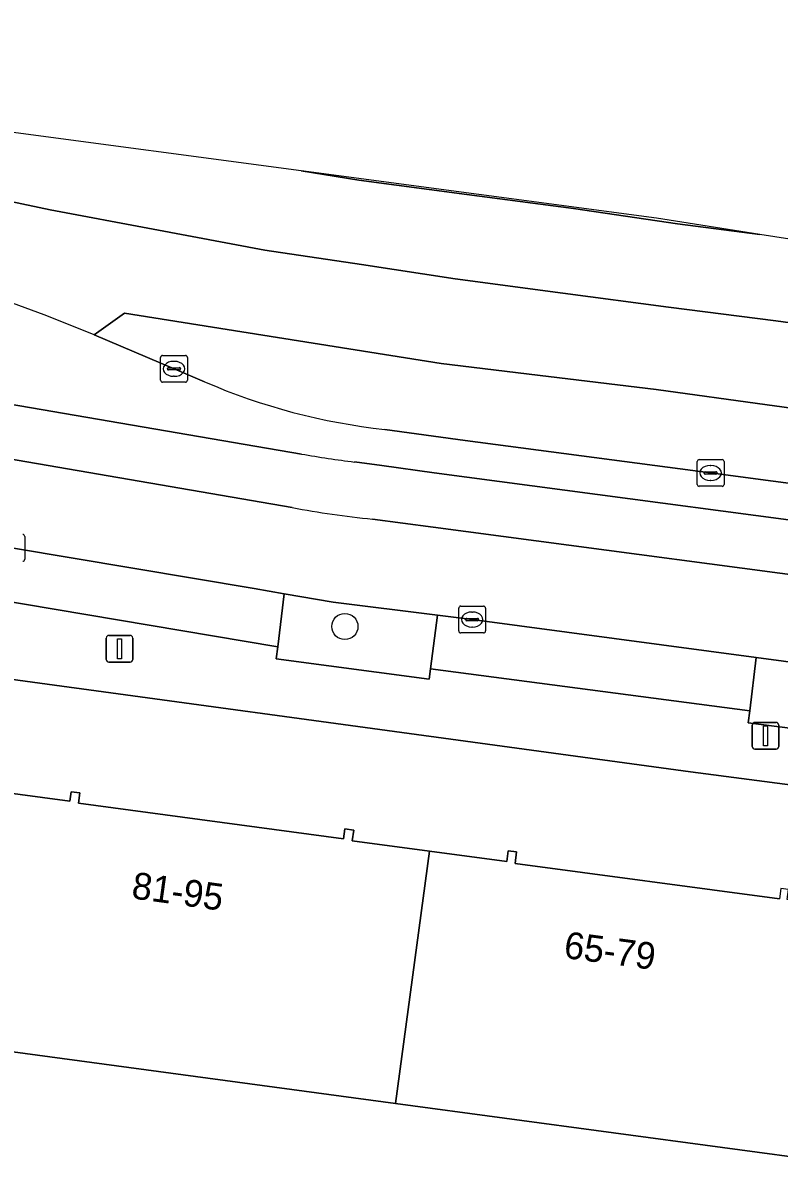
# Model space of a CAD drawing. Extents: x 161258 to 161838, y 380833 to 381727.
# Drawn here: x 161691.79 to 161720.06, y 381630.65 to 381673.22 of the extents above; entities that cross this region are included whole.
import ezdxf

# ---------------------------------------------------------------- set-up
doc = ezdxf.new("R2010")
doc.units = 0
for name, color, linetype in [('IMGEO_Berm_groen', 7, 'Continuous'), ('IMGEO_Boom', 7, 'Continuous'), ('IMGEO_Erf', 7, 'Continuous'), ('IMGEO_Groenvoorziening', 7, 'Continuous'), ('IMGEO_Kolk', 7, 'Continuous'), ('IMGEO_Lichtmast', 7, 'Continuous'), ('IMGEO_Pand', 7, 'Continuous'), ('IMGEO_Pand_nummerreeks', 7, 'Continuous'), ('IMGEO_Parkeervlak_halfverhard', 7, 'Continuous'), ('IMGEO_Parkeervlak_open', 7, 'Continuous'), ('IMGEO_Rijbaan_lokaal_open', 7, 'Continuous'), ('IMGEO_Rijbaan_regionaal_gesloten', 7, 'Continuous'), ('IMGEO_Voetpad_open', 7, 'Continuous')]:
    doc.layers.add(name, color=color, linetype=linetype)

msp = doc.modelspace()

# ---------------------------------------------------------------- linework, layer by layer
at = {"layer": 'IMGEO_Berm_groen'}
for points in [[(161698.584, 381659.806), (161697.441, 381660.29), (161694.46, 381661.561)], [(161690.364, 381659.132), (161702.211, 381657.106)], [(161751.562, 381651.859), (161748.27, 381652.294), (161735.854, 381653.957), (161717.493, 381656.402), (161708.326, 381657.615), (161705.319, 381658.026)], [(161704.19, 381656.809), (161705.202, 381656.678), (161707.162, 381656.402), (161745.844, 381651.267), (161745.561, 381649.28), (161747.771, 381648.987), (161748.384, 381648.906)]]:
    msp.add_lwpolyline(points, dxfattribs=at)
for centre, radius, start, end in [((161666.124, 381592.694), 74.469, 67.63445, 80.03744), ((161707.843, 381681.209), 23.32, 246.6057, 263.7858), ((161709.103, 381696.289), 39.785, 260.0239, 262.9061)]:
    msp.add_arc(centre, radius, start, end, dxfattribs=at)
at = {"layer": 'IMGEO_Boom'}
msp.add_circle((161703.825, 381650.663), 0.489, dxfattribs=at)
at = {"layer": 'IMGEO_Erf'}
for points in [[(161744.895, 381638.467), (161745.302, 381641.497), (161740.472, 381642.131), (161716.743, 381645.239), (161684.01, 381649.696), (161663.105, 381652.447), (161611.247, 381659.449), (161599.202, 381661.023)], [(161690.653, 381644.528), (161693.554, 381644.137), (161693.602, 381644.489), (161693.926, 381644.446), (161693.874, 381644.065), (161703.771, 381642.732), (161703.82, 381643.1), (161704.157, 381643.055), (161704.104, 381642.658), (161706.989, 381642.27), (161709.875, 381641.881), (161709.929, 381642.284), (161710.245, 381642.241), (161710.187, 381641.813), (161720.07, 381640.482)], [(161722.012, 381630.648), (161705.72, 381632.842), (161689.376, 381635.044)]]:
    msp.add_lwpolyline(points, dxfattribs=at)
at = {"layer": 'IMGEO_Groenvoorziening'}
for points in [[(161707.291, 381651.084), (161703.394, 381651.569), (161701.559, 381651.889), (161701.316, 381649.903), (161701.262, 381649.458), (161706.977, 381648.699), (161707.027, 381649.08)], [(161723.091, 381648.984), (161719.195, 381649.505), (161718.952, 381647.508), (161718.897, 381647.059), (161722.791, 381646.567), (161722.845, 381647.001)]]:
    msp.add_lwpolyline(points, close=True, dxfattribs=at)
at = {"layer": 'IMGEO_Kolk'}
for p, q in [((161696.94, 381659.864), (161696.94, 381660.716)), ((161697.015, 381660.79), (161697.867, 381660.79)), ((161697.941, 381660.716), (161697.941, 381659.864)), ((161697.199, 381660.284), (161697.199, 381660.296)), ((161697.637, 381660.247), (161697.239, 381660.247)), ((161697.242, 381660.333), (161697.64, 381660.333)), ((161697.428, 381660.57), (161697.453, 381660.57)), ((161697.683, 381660.296), (161697.683, 381660.284)), ((161697.867, 381659.79), (161697.015, 381659.79)), ((161697.451, 381660.01), (161697.426, 381660.01)), ((161716.992, 381655.974), (161716.992, 381656.826)), ((161717.067, 381656.9), (161717.919, 381656.9)), ((161717.993, 381656.826), (161717.993, 381655.974)), ((161717.251, 381656.394), (161717.251, 381656.406)), ((161717.689, 381656.357), (161717.291, 381656.357)), ((161717.294, 381656.443), (161717.692, 381656.443)), ((161717.48, 381656.68), (161717.505, 381656.68)), ((161717.735, 381656.406), (161717.735, 381656.394)), ((161717.503, 381656.12), (161717.478, 381656.12)), ((161717.919, 381655.9), (161717.067, 381655.9)), ((161691.864, 381654.026), (161691.864, 381653.174)), ((161708.08, 381650.497), (161708.08, 381651.349)), ((161708.155, 381651.423), (161709.007, 381651.423)), ((161709.081, 381651.349), (161709.081, 381650.497)), ((161708.339, 381650.917), (161708.339, 381650.929)), ((161708.777, 381650.88), (161708.379, 381650.88)), ((161708.382, 381650.966), (161708.78, 381650.966)), ((161708.568, 381651.203), (161708.593, 381651.203)), ((161708.823, 381650.929), (161708.823, 381650.917)), ((161709.007, 381650.423), (161708.155, 381650.423)), ((161708.591, 381650.643), (161708.566, 381650.643))]:
    msp.add_line(p, q, dxfattribs=at)
for points in [[(161696.94, 381659.864), (161696.94, 381660.716)], [(161697.015, 381660.79), (161697.867, 381660.79)], [(161697.941, 381660.716), (161697.941, 381659.864)], [(161697.867, 381659.79), (161697.015, 381659.79)], [(161716.992, 381655.974), (161716.992, 381656.826)], [(161717.067, 381656.9), (161717.919, 381656.9)], [(161717.993, 381656.826), (161717.993, 381655.974)], [(161717.919, 381655.9), (161717.067, 381655.9)], [(161691.864, 381654.026), (161691.864, 381653.174)], [(161708.08, 381650.497), (161708.08, 381651.349)], [(161708.155, 381651.423), (161709.007, 381651.423)], [(161709.081, 381651.349), (161709.081, 381650.497)], [(161709.007, 381650.423), (161708.155, 381650.423)]]:
    msp.add_lwpolyline(points, dxfattribs=at)
for centre, radius, start, end in [((161697.017, 381660.714), 0.0765, 91.552, 178.448), ((161697.017, 381660.714), 0.0765, 91.552, 178.448), ((161697.865, 381660.714), 0.0765, 1.552, 88.448), ((161697.865, 381660.714), 0.0765, 1.552, 88.448), ((161697.239, 381660.293), 0.0403, 85.8775, 175.7526), ((161697.236, 381660.283), 0.0366, 178.938, 274.7102), ((161697.64, 381660.29), 0.043, 264.8664, 352.4533), ((161697.644, 381660.295), 0.0386, 1.7309, 96.639), ((161697.017, 381659.866), 0.0765, 181.552, 268.448), ((161697.017, 381659.866), 0.0765, 181.552, 268.448), ((161697.865, 381659.866), 0.0765, 271.552, 358.448), ((161697.865, 381659.866), 0.0765, 271.552, 358.448), ((161717.069, 381656.824), 0.0765, 91.552, 178.448), ((161717.069, 381656.824), 0.0765, 91.552, 178.448), ((161717.917, 381656.824), 0.0765, 1.552, 88.448), ((161717.917, 381656.824), 0.0765, 1.552, 88.448), ((161717.291, 381656.403), 0.0403, 85.8775, 175.7526), ((161717.288, 381656.393), 0.0366, 178.938, 274.7102), ((161717.692, 381656.4), 0.043, 264.8664, 352.4533), ((161717.696, 381656.405), 0.0386, 1.7309, 96.639), ((161717.069, 381655.976), 0.0765, 181.552, 268.448), ((161717.069, 381655.976), 0.0765, 181.552, 268.448), ((161717.917, 381655.976), 0.0765, 271.552, 358.448), ((161717.917, 381655.976), 0.0765, 271.552, 358.448), ((161691.788, 381654.024), 0.0765, 1.552, 88.448), ((161691.788, 381654.024), 0.0765, 1.552, 88.448), ((161691.788, 381653.176), 0.0765, 271.552, 358.448), ((161691.788, 381653.176), 0.0765, 271.552, 358.448), ((161708.157, 381651.347), 0.0765, 91.552, 178.448), ((161708.157, 381651.347), 0.0765, 91.552, 178.448), ((161709.005, 381651.347), 0.0765, 1.552, 88.448), ((161709.005, 381651.347), 0.0765, 1.552, 88.448), ((161708.379, 381650.926), 0.0403, 85.8775, 175.7526), ((161708.376, 381650.916), 0.0366, 178.938, 274.7102), ((161708.78, 381650.923), 0.043, 264.8664, 352.4533), ((161708.784, 381650.928), 0.0386, 1.7309, 96.639), ((161708.157, 381650.499), 0.0765, 181.552, 268.448), ((161708.157, 381650.499), 0.0765, 181.552, 268.448), ((161709.005, 381650.499), 0.0765, 271.552, 358.448), ((161709.005, 381650.499), 0.0765, 271.552, 358.448)]:
    msp.add_arc(centre, radius, start, end, dxfattribs=at)
for centre, major_axis, ratio, start_param, end_param in [((161697.427, 381660.29), (-0.387, 0.002), 0.722429, 4.712389, 7.853982), ((161697.452, 381660.29), (-0.39, 0.002), 0.717154, 1.570796, 4.712389), ((161717.479, 381656.4), (-0.387, 0.002), 0.722429, 4.712389, 7.853982), ((161717.504, 381656.4), (-0.39, 0.002), 0.717154, 1.570796, 4.712389), ((161708.567, 381650.923), (-0.387, 0.002), 0.722429, 4.712389, 7.853982), ((161708.592, 381650.923), (-0.39, 0.002), 0.717154, 1.570796, 4.712389)]:
    msp.add_ellipse(centre, major_axis=major_axis, ratio=ratio, start_param=start_param, end_param=end_param, dxfattribs=at)
at = {"layer": 'IMGEO_Lichtmast'}
for p, q in [((161694.91, 381649.432), (161694.91, 381650.232)), ((161694.91, 381650.232), (161694.91, 381649.432)), ((161695.01, 381650.332), (161695.8, 381650.332)), ((161695.8, 381650.332), (161695.01, 381650.332)), ((161695.9, 381650.232), (161695.9, 381649.432)), ((161695.9, 381649.432), (161695.9, 381650.232)), ((161695.8, 381649.332), (161695.01, 381649.332)), ((161695.01, 381649.332), (161695.8, 381649.332)), ((161719.049, 381646.181), (161719.049, 381646.981)), ((161719.049, 381646.981), (161719.049, 381646.181)), ((161719.149, 381647.081), (161719.939, 381647.081)), ((161719.939, 381647.081), (161719.149, 381647.081)), ((161720.039, 381646.981), (161720.039, 381646.181)), ((161720.039, 381646.181), (161720.039, 381646.981)), ((161719.939, 381646.081), (161719.149, 381646.081)), ((161719.149, 381646.081), (161719.939, 381646.081))]:
    msp.add_line(p, q, dxfattribs=at)
for points in [[(161695.33, 381650.207), (161695.48, 381650.207), (161695.48, 381649.457), (161695.33, 381649.457), (161695.33, 381650.207)], [(161719.469, 381646.956), (161719.619, 381646.956), (161719.619, 381646.206), (161719.469, 381646.206), (161719.469, 381646.956)]]:
    msp.add_lwpolyline(points, dxfattribs=at)
for centre, start, end in [((161695.01, 381650.232), 90, 180), ((161695.01, 381650.232), 90, 180), ((161695.8, 381650.232), 0, 90), ((161695.8, 381650.232), 360, 90), ((161695.01, 381649.432), 180, 270), ((161695.01, 381649.432), 180, 270), ((161695.8, 381649.432), 270, 0), ((161695.8, 381649.432), 270, 0), ((161719.149, 381646.981), 90, 180), ((161719.149, 381646.981), 90, 180), ((161719.939, 381646.981), 0, 90), ((161719.939, 381646.981), 360, 90), ((161719.149, 381646.181), 180, 270), ((161719.149, 381646.181), 180, 270), ((161719.939, 381646.181), 270, 0), ((161719.939, 381646.181), 270, 0)]:
    msp.add_arc(centre, 0.1, start, end, dxfattribs=at)
at = {"layer": 'IMGEO_Pand'}
for points in [[(161689.376, 381635.044), (161705.72, 381632.842), (161706.989, 381642.27), (161704.104, 381642.658), (161704.157, 381643.055), (161703.82, 381643.1), (161703.771, 381642.732), (161693.874, 381644.065), (161693.926, 381644.446), (161693.602, 381644.489), (161693.554, 381644.137), (161690.653, 381644.528)], [(161723.281, 381640.073), (161720.357, 381640.466), (161720.407, 381640.837), (161720.122, 381640.875), (161720.07, 381640.482), (161710.187, 381641.813), (161710.245, 381642.241), (161709.929, 381642.284), (161709.875, 381641.881), (161706.989, 381642.27), (161705.72, 381632.842), (161722.012, 381630.648)]]:
    msp.add_lwpolyline(points, close=True, dxfattribs=at)
at = {"layer": 'IMGEO_Parkeervlak_halfverhard'}
for points in [[(161702.211, 381657.106), (161690.364, 381659.132)], [(161690.043, 381657.133), (161701.851, 381655.11)], [(161704.858, 381654.679), (161707.129, 381654.372), (161743.167, 381649.597), (161745.561, 381649.28), (161745.844, 381651.267), (161707.162, 381656.402), (161705.202, 381656.678), (161704.19, 381656.809)]]:
    msp.add_lwpolyline(points, dxfattribs=at)
for centre, radius, start, end in [((161709.103, 381696.289), 39.785, 260.0239, 262.9061), ((161707.649, 381684.859), 30.309, 258.9708, 264.7157)]:
    msp.add_arc(centre, radius, start, end, dxfattribs=at)
at = {"layer": 'IMGEO_Parkeervlak_open'}
msp.add_lwpolyline([(161683.714, 381654.721), (161683.461, 381652.77), (161688.212, 381652.107), (161701.316, 381649.903), (161701.559, 381651.889), (161700.442, 381652.083), (161691.364, 381653.6), (161690.111, 381653.815)], dxfattribs=at)
msp.add_lwpolyline([(161719.195, 381649.505), (161708.581, 381650.923), (161707.291, 381651.084), (161707.027, 381649.08), (161718.952, 381647.508)], close=True, dxfattribs=at)
at = {"layer": 'IMGEO_Rijbaan_lokaal_open'}
for points in [[(161701.851, 381655.11), (161690.043, 381657.133)], [(161690.111, 381653.815), (161691.364, 381653.6), (161700.442, 381652.083), (161701.559, 381651.889), (161703.394, 381651.569), (161707.291, 381651.084), (161708.581, 381650.923), (161719.195, 381649.505), (161723.091, 381648.984), (161723.895, 381648.877), (161734.952, 381647.415), (161738.052, 381647.005), (161742.805, 381646.376), (161743.167, 381649.597), (161707.129, 381654.372), (161704.858, 381654.679)]]:
    msp.add_lwpolyline(points, dxfattribs=at)
msp.add_arc((161707.649, 381684.859), 30.309, 258.9708, 264.7157, dxfattribs=at)
at = {"layer": 'IMGEO_Rijbaan_regionaal_gesloten'}
for points in [[(161736.137, 381662.69), (161719.327, 381665.313), (161716.253, 381665.701), (161712.371, 381666.274), (161708.386, 381666.804), (161704.351, 381667.34), (161702.189, 381667.689), (161690.967, 381669.187), (161665.691, 381672.562), (161583.995, 381683.424), (161565.314, 381685.907), (161412.782, 381706.187)], [(161723.875, 381661.551), (161719.934, 381662.085), (161715.913, 381662.59), (161711.965, 381663.118), (161707.95, 381663.655), (161704.447, 381664.184), (161700.839, 381664.728), (161696.656, 381665.513), (161692.816, 381666.233), (161688.805, 381667.074), (161684.795, 381667.916), (161680.859, 381668.646), (161668.901, 381670.395), (161656.473, 381672.064), (161640.688, 381674.185), (161624.53, 381676.356), (161612.423, 381677.982), (161592.223, 381680.696), (161572.343, 381683.367), (161560.228, 381684.995), (161544.014, 381687.173)], [(161544.014, 381687.173), (161560.228, 381684.995), (161572.343, 381683.367), (161592.223, 381680.696), (161612.423, 381677.982), (161624.53, 381676.356), (161640.688, 381674.185), (161656.473, 381672.064), (161668.901, 381670.395), (161680.859, 381668.646), (161684.795, 381667.916), (161688.805, 381667.074), (161692.816, 381666.233), (161696.656, 381665.513), (161700.839, 381664.728), (161704.447, 381664.184), (161707.95, 381663.655), (161711.965, 381663.118), (161715.913, 381662.59), (161719.934, 381662.085), (161723.875, 381661.551)], [(161719.327, 381665.313), (161715.466, 381665.916), (161702.189, 381667.689), (161704.351, 381667.34), (161708.386, 381666.804), (161712.371, 381666.274), (161716.253, 381665.701), (161719.327, 381665.313)], [(161694.46, 381661.561), (161695.592, 381662.368), (161699.432, 381661.756), (161703.427, 381661.121), (161707.421, 381660.485), (161711.437, 381660.002), (161715.452, 381659.519), (161719.602, 381658.939), (161727.522, 381657.865)], [(161727.522, 381657.865), (161719.602, 381658.939), (161715.452, 381659.519), (161711.437, 381660.002), (161707.421, 381660.485), (161703.427, 381661.121), (161699.432, 381661.756), (161695.592, 381662.368), (161694.46, 381661.561)], [(161694.46, 381661.561), (161697.441, 381660.29), (161698.584, 381659.806)], [(161705.319, 381658.026), (161708.326, 381657.615), (161717.493, 381656.402), (161735.854, 381653.957)]]:
    msp.add_lwpolyline(points, dxfattribs=at)
for centre, radius, start, end in [((161666.124, 381592.694), 74.469, 67.63445, 80.03744), ((161707.843, 381681.209), 23.32, 246.6057, 263.7858)]:
    msp.add_arc(centre, radius, start, end, dxfattribs=at)
at = {"layer": 'IMGEO_Voetpad_open'}
for points in [[(161599.202, 381661.023), (161611.247, 381659.449), (161663.105, 381652.447), (161684.01, 381649.696), (161716.743, 381645.239), (161740.472, 381642.131), (161745.302, 381641.497), (161747.796, 381641.17), (161747.999, 381642.867)], [(161745.165, 381646.064), (161744.037, 381646.213), (161743.759, 381644.23), (161742.226, 381644.447), (161737.79, 381645.057), (161737.724, 381644.566), (161734.62, 381645.002), (161734.683, 381645.463), (161722.845, 381647.001), (161722.791, 381646.567), (161718.897, 381647.059), (161718.952, 381647.508), (161707.027, 381649.08), (161706.977, 381648.699), (161701.262, 381649.458), (161701.316, 381649.903), (161688.212, 381652.107), (161683.461, 381652.77)]]:
    msp.add_lwpolyline(points, dxfattribs=at)

# ---------------------------------------------------------------- texts
at = {"layer": 'IMGEO_Pand_nummerreeks'}
for s, rotation, p in [('81-95', 352.0881, (161695.822, 381640.511)), ('65-79', 352.3255, (161711.973, 381638.287))]:
    msp.add_text(s, height=1, rotation=rotation, dxfattribs=at).set_placement(p)

doc.saveas('drawing.dxf')
